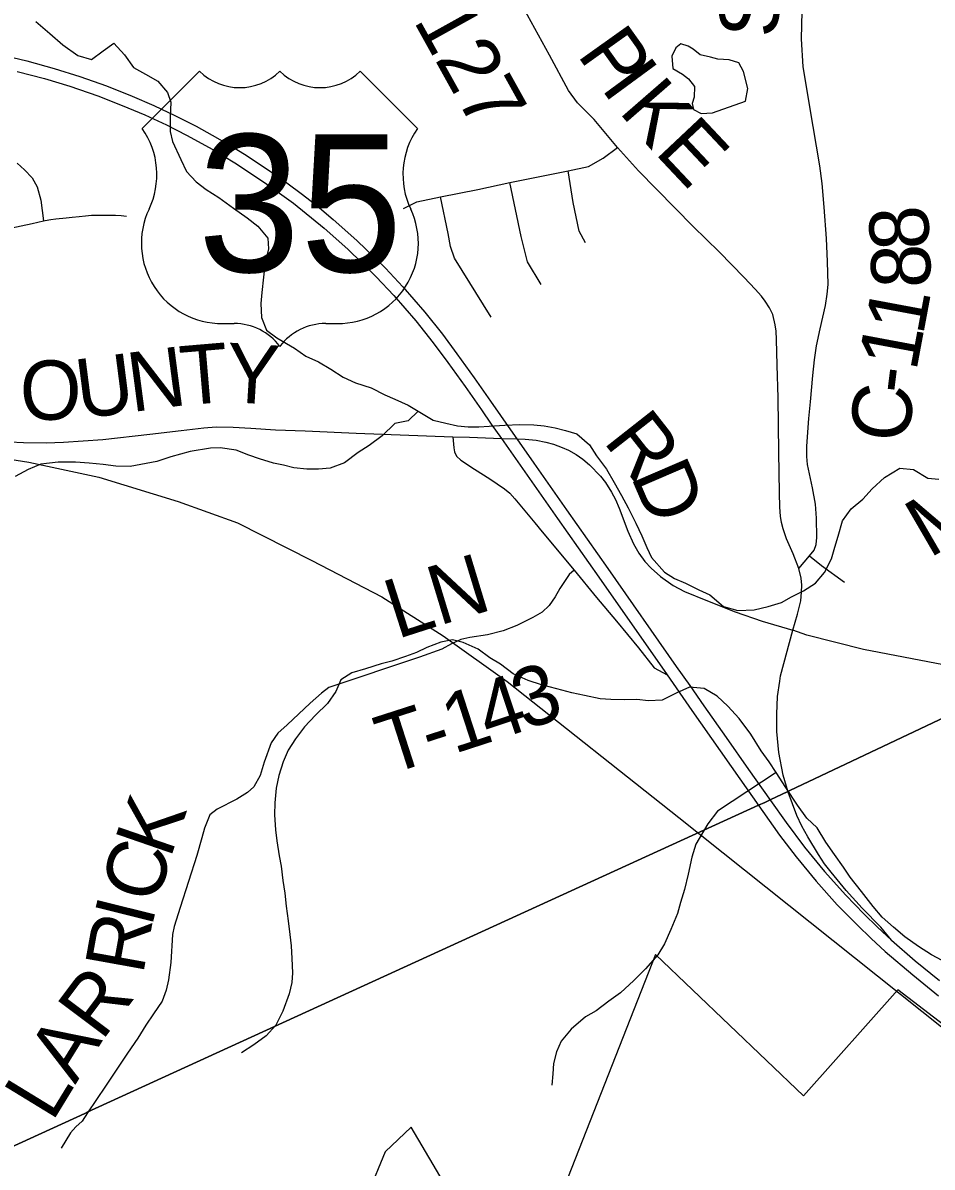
# Model space of a CAD drawing. Extents: x 0 to 34, y 0 to 22.
# Drawn here: x 2.449 to 3.32, y 16.134 to 17.231 of the extents above; entities that cross this region are included whole.
import ezdxf

# ---------------------------------------------------------------- set-up
doc = ezdxf.new("R2010")
doc.units = 0
for name, color, linetype in [('GM_X_Corporation', 7, 'Continuous'), ('GM_X_County_Road', 7, 'Continuous'), ('GM_X_County_Road_Text', 7, 'Continuous'), ('GM_X_Interchange_Ramps', 7, 'Continuous'), ('GM_X_Minor_Lake', 7, 'Continuous'), ('GM_X_Minor_River', 7, 'Continuous'), ('GM_X_Rail_Line', 7, 'Continuous'), ('GM_X_Township_Road', 7, 'Continuous'), ('GM_X_Township_Road_Text', 7, 'Continuous'), ('GM_X_US_Location', 7, 'Continuous'), ('GM_X_US_Route', 7, 'Continuous'), ('GM_X_US_Shield', 7, 'Continuous'), ('SH_Data', 7, 'Continuous')]:
    doc.layers.add(name, color=color, linetype=linetype)

msp = doc.modelspace()

# ---------------------------------------------------------------- linework, layer by layer
at = {"layer": 'GM_X_Corporation'}
for points in [[(2.1, 20.9), (2.1, 15.9991), (2.5081, 16.1858), (2.5106, 16.1869), (3.1538, 16.4811), (3.1598, 16.4838), (3.1648, 16.4862), (3.1819, 16.4943), (3.1836, 16.4951), (3.3801, 16.588), (3.8146, 16.7867), (3.8864, 16.8187), (4.2007, 16.9645), (4.2041, 17.0039), (4.5514, 17.1703), (4.4931, 17.1874), (4.4442, 17.208), (4.4091, 17.232)], [(3.3801, 16.588), (3.1836, 16.4951), (3.1819, 16.4943), (3.1648, 16.4862), (3.1598, 16.4838), (3.1538, 16.4811), (2.5106, 16.1869), (2.5081, 16.1858), (2.1, 15.9991), (2.1, 14.1), (7.2283, 14.1)], [(3.5673, 16.0897), (3.2872, 16.3043), (3.197, 16.2026), (3.0551, 16.3381), (2.9469, 16.0625), (2.8663, 16.0956), (2.8209, 16.1726), (2.7961, 16.1489), (2.7147, 15.9511), (2.6512, 15.9557), (2.5715, 15.9232), (2.6113, 15.828), (2.6287, 15.7341), (2.5959, 15.6539), (2.3763, 15.7531), (2.1188, 15.8705), (2.1, 15.8606), (2.1, 15.2015)]]:
    msp.add_lwpolyline(points, dxfattribs=at)
at = {"layer": 'GM_X_County_Road'}
for points in [[(3.1924, 16.708), (3.2025, 16.7202), (3.207, 16.7256), (3.209, 16.7308), (3.2097, 16.7375), (3.2092, 16.7562), (3.2082, 16.7695), (3.2056, 16.7852), (3.2026, 16.7986), (3.2007, 16.8076), (3.2, 16.8152), (3.2, 16.825), (3.2019, 16.8517), (3.2035, 16.8677), (3.2059, 16.8929), (3.2074, 16.908), (3.2094, 16.9214), (3.2129, 16.9376), (3.2178, 16.96), (3.2196, 16.9707), (3.2204, 16.9799), (3.2197, 17.0022), (3.2188, 17.024), (3.2168, 17.0542), (3.2147, 17.0769), (3.2125, 17.0938), (3.2061, 17.1313), (3.1965, 17.1886), (3.1948, 17.2155), (3.1976, 17.3201)], [(3.1865, 16.6487), (3.191, 16.6643), (3.1943, 16.6769), (3.195, 16.6852), (3.1952, 16.6921), (3.1947, 16.6988), (3.1924, 16.708), (3.1869, 16.7219), (3.1807, 16.7362), (3.1774, 16.7458), (3.1757, 16.7519), (3.1748, 16.7581), (3.1743, 16.7666), (3.1739, 16.7803), (3.1733, 16.8195), (3.1725, 16.8716), (3.1717, 16.9026), (3.1711, 16.9274), (3.1706, 16.9353), (3.1698, 16.9415), (3.1673, 16.9512), (3.1644, 16.9577), (3.1601, 16.964), (3.1566, 16.9688), (3.1504, 16.9757), (3.14, 16.9867), (3.1161, 17.0114), (3.0912, 17.0356), (3.0386, 17.089), (3.0186, 17.1112), (2.9961, 17.1381), (2.9803, 17.154), (2.9717, 17.166), (2.9533, 17.1998), (2.9112, 17.2768)], [(2.4362, 16.8293), (2.4495, 16.8285), (2.4713, 16.8284), (2.4877, 16.8289), (2.5255, 16.8316), (2.5704, 16.8367), (2.6005, 16.8402), (2.6222, 16.8428), (2.634, 16.8437), (2.6505, 16.8433), (2.6674, 16.8423), (2.6909, 16.8409), (2.7192, 16.8397), (2.7683, 16.8377), (2.8609, 16.8342), (2.8769, 16.8337), (2.9074, 16.8326), (2.9221, 16.8321), (2.9302, 16.8318), (2.9407, 16.8308), (2.9498, 16.8291), (2.9573, 16.8272), (2.9657, 16.824), (2.9717, 16.8213), (2.979, 16.8172), (2.9854, 16.8127), (2.9919, 16.8071), (3.0023, 16.7964), (3.007, 16.7903), (3.0128, 16.7812), (3.0168, 16.774), (3.0201, 16.7657), (3.0284, 16.7436), (3.0338, 16.7314), (3.039, 16.7227), (3.0449, 16.7147), (3.0508, 16.7084), (3.0599, 16.7001), (3.072, 16.6916), (3.0827, 16.686), (3.1047, 16.677), (3.1314, 16.6663), (3.1573, 16.6576), (3.1865, 16.6487)], [(3.2025, 16.7202), (3.2141, 16.7109), (3.236, 16.6948)], [(3.3378, 16.6142), (3.3161, 16.6186), (3.2542, 16.6304), (3.1999, 16.6441), (3.1865, 16.6487)]]:
    msp.add_lwpolyline(points, dxfattribs=at)
at = {"layer": 'GM_X_Interchange_Ramps'}
for points in [[(2.9772, 16.7064), (2.9986, 16.6802), (3.0175, 16.6576), (3.0386, 16.6318), (3.0539, 16.6129), (3.0662, 16.6059)], [(3.1741, 16.5999), (3.1749, 16.6051), (3.1865, 16.6487)], [(3.2811, 16.3517), (3.2709, 16.3642), (3.2532, 16.3824), (3.2377, 16.3995), (3.2233, 16.4169), (3.2171, 16.425), (3.2111, 16.434), (3.2009, 16.4507), (3.1953, 16.461), (3.1906, 16.4713), (3.1821, 16.4937), (3.1775, 16.5099), (3.1733, 16.5316), (3.1714, 16.5518), (3.1712, 16.5682), (3.172, 16.5854), (3.1741, 16.5999)]]:
    msp.add_lwpolyline(points, dxfattribs=at)
at = {"layer": 'GM_X_Minor_Lake'}
for points in [[(3.1413, 17.1556), (3.1434, 17.1677), (3.1394, 17.1841), (3.1349, 17.1924), (3.1255, 17.1952), (3.1149, 17.196), (3.1077, 17.198), (3.0979, 17.2), (3.0911, 17.2054), (3.0862, 17.2085), (3.0794, 17.2108), (3.0745, 17.2067), (3.0706, 17.1987), (3.0716, 17.187), (3.081, 17.1816), (3.0866, 17.177), (3.0923, 17.1697), (3.0921, 17.1594), (3.0902, 17.1534), (3.0916, 17.1477), (3.0988, 17.1438), (3.1098, 17.1445)], [(3.1098, 17.1445), (3.1413, 17.1556)]]:
    msp.add_lwpolyline(points, dxfattribs=at)
at = {"layer": 'GM_X_Minor_River'}
for points in [[(2.4612, 17.232), (2.4747, 17.2205), (2.4871, 17.2098), (2.5014, 17.1994), (2.5146, 17.1955), (2.5257, 17.2041), (2.536, 17.2112), (2.5461, 17.2001), (2.5547, 17.1879), (2.5663, 17.1817), (2.578, 17.1748), (2.5874, 17.1641), (2.5907, 17.1546), (2.5901, 17.1405), (2.59, 17.1265), (2.5922, 17.117), (2.6003, 17.0998), (2.6055, 17.0884), (2.6149, 17.0785), (2.6246, 17.0712), (2.6367, 17.0635), (2.6506, 17.0531), (2.6637, 17.0439), (2.6739, 17.0358), (2.6836, 17.0243), (2.6843, 17.0141), (2.6811, 17.0012), (2.6794, 16.9872), (2.6778, 16.9724), (2.6769, 16.9618), (2.6775, 16.9485), (2.6823, 16.9363), (2.6921, 16.929), (2.709, 16.919), (2.7199, 16.9113), (2.732, 16.9059), (2.744, 16.8989), (2.7557, 16.8912), (2.7677, 16.8858), (2.7825, 16.8811), (2.7956, 16.8742), (2.8054, 16.8703), (2.8179, 16.8645), (2.8277, 16.8587), (2.842, 16.8502), (2.8541, 16.8471), (2.8654, 16.8447), (2.8756, 16.8438), (2.8858, 16.8437), (2.8957, 16.8444), (2.9108, 16.8454), (2.9249, 16.846), (2.9385, 16.8455), (2.9483, 16.8447), (2.9589, 16.8427), (2.9687, 16.8403), (2.9797, 16.8368), (2.9917, 16.8265), (2.9984, 16.8158), (3.0081, 16.8032), (3.0155, 16.7902), (3.0226, 16.778), (3.0289, 16.7662), (3.0363, 16.7513), (3.0419, 16.7391), (3.0467, 16.7281), (3.0512, 16.7185), (3.0635, 16.7044), (3.0733, 16.6982), (3.0838, 16.6939), (3.0967, 16.6874), (3.1072, 16.6827), (3.1203, 16.6716), (3.1339, 16.6677), (3.1495, 16.6683), (3.1631, 16.6716), (3.1757, 16.6753), (3.1852, 16.6809), (3.197, 16.6864), (3.2084, 16.6939), (3.2169, 16.7041), (3.2238, 16.7173), (3.227, 16.7283), (3.2301, 16.7389), (3.2341, 16.7536), (3.2425, 16.765), (3.2536, 16.7743), (3.2628, 16.7841), (3.2743, 16.795), (3.2891, 16.804), (3.3024, 16.8027), (3.3159, 16.7946), (3.3265, 16.7934)], [(2.8277, 16.8587), (2.8181, 16.8493), (2.8052, 16.8468), (2.793, 16.8351), (2.7807, 16.8257), (2.7701, 16.819), (2.7571, 16.8093), (2.7434, 16.8041), (2.732, 16.803), (2.721, 16.8031), (2.7086, 16.8044), (2.6987, 16.8068), (2.6889, 16.8088), (2.6757, 16.813), (2.6655, 16.8166), (2.6531, 16.8212), (2.6379, 16.8236), (2.6285, 16.8233), (2.6091, 16.8201), (2.5905, 16.815), (2.5772, 16.8105), (2.567, 16.8084), (2.5518, 16.8055), (2.5378, 16.806), (2.5257, 16.8076), (2.5124, 16.8089), (2.4992, 16.8097), (2.4825, 16.8099), (2.4662, 16.8078), (2.454, 16.8029), (2.4415, 16.7962)], [(3.3296, 16.3323), (3.3195, 16.3377), (3.307, 16.3458), (3.2939, 16.3551), (3.283, 16.3643), (3.2721, 16.3738), (3.2635, 16.3842), (3.2523, 16.3983), (3.2415, 16.4121), (3.2351, 16.4216), (3.2265, 16.4338), (3.2183, 16.4457), (3.2098, 16.4594), (3.2, 16.4686), (3.1911, 16.4812), (3.1799, 16.498), (3.1706, 16.5125), (3.1638, 16.5228), (3.1564, 16.5331), (3.1463, 16.5492), (3.1351, 16.5641), (3.1243, 16.5759), (3.1141, 16.5855), (3.1017, 16.5928), (3.0877, 16.5941), (3.0748, 16.5885), (3.0615, 16.5818), (3.0482, 16.5812), (3.0372, 16.5824), (3.0251, 16.5822), (3.0122, 16.5823), (3.002, 16.5831), (2.9869, 16.5863), (2.9748, 16.5887), (2.9605, 16.5926), (2.9457, 16.5966), (2.9329, 16.6005), (2.9186, 16.607), (2.9065, 16.6163), (2.8964, 16.6224), (2.8851, 16.6305), (2.8708, 16.6371), (2.8606, 16.6395), (2.8492, 16.6373), (2.8359, 16.6321), (2.826, 16.6273), (2.8154, 16.6236), (2.8024, 16.6191), (2.7922, 16.6166), (2.777, 16.6118), (2.7641, 16.6081), (2.7534, 16.6014), (2.7487, 16.59), (2.7407, 16.5787), (2.7292, 16.5674), (2.7188, 16.5561), (2.71, 16.5448), (2.7031, 16.5339), (2.6984, 16.5226), (2.6941, 16.5097), (2.6917, 16.4976), (2.6904, 16.4835), (2.6899, 16.4718), (2.6909, 16.4574), (2.6923, 16.4471), (2.6944, 16.4327), (2.6962, 16.4228), (2.698, 16.4091)], [(3.1706, 16.5125), (3.1145, 16.4755), (3.1053, 16.4634), (3.0937, 16.4438), (3.0898, 16.4313), (3.0862, 16.415), (3.0827, 16.4003), (3.0791, 16.3878), (3.076, 16.3775), (3.0698, 16.362), (3.0635, 16.3484), (3.0574, 16.3379), (3.0455, 16.3243), (3.0344, 16.313), (3.0214, 16.3014), (3.0103, 16.2935), (2.9981, 16.2842), (2.9878, 16.2782), (2.9741, 16.2665), (2.9645, 16.2549), (2.9602, 16.2447), (2.9574, 16.2337), (2.9566, 16.2238), (2.9557, 16.2128)], [(2.698, 16.4091), (2.6997, 16.3969), (2.7011, 16.3844), (2.7029, 16.3704), (2.7046, 16.3571), (2.706, 16.3464), (2.7066, 16.3343), (2.7073, 16.3206), (2.7064, 16.3111), (2.704, 16.3005), (2.6978, 16.2839), (2.6912, 16.2703), (2.682, 16.2601), (2.6702, 16.2515), (2.6584, 16.244)]]:
    msp.add_lwpolyline(points, dxfattribs=at)
at = {"layer": 'GM_X_Rail_Line'}
msp.add_lwpolyline([(2.1, 16.8228), (2.1358, 16.8282), (2.1875, 16.8321), (2.2635, 16.8323), (2.3249, 16.8251), (2.3996, 16.8184), (2.4546, 16.8097), (2.5216, 16.7954), (2.5976, 16.772), (2.6544, 16.7517), (2.7256, 16.7157), (2.7928, 16.6809), (2.8517, 16.6435), (2.9129, 16.5996), (3.0775, 16.4694), (3.2031, 16.3691), (3.3322, 16.2662), (3.4651, 16.1627), (3.5695, 16.0783), (3.7315, 15.9489), (3.9997, 15.7391), (4.1856, 15.5884)], dxfattribs=at)
at = {"layer": 'GM_X_Township_Road'}
for points in [[(2.8136, 17.053), (2.8263, 17.0594), (2.8489, 17.0639), (2.8849, 17.071), (2.9154, 17.0778), (2.9713, 17.089), (2.9909, 17.0932), (3.0048, 17.101), (3.0186, 17.1112)], [(2.4433, 17.0963), (2.4505, 17.0899), (2.4579, 17.0821), (2.4624, 17.0736), (2.466, 17.0607), (2.4687, 17.041)], [(2.9878, 17.0199), (2.9818, 17.0312), (2.9762, 17.0586), (2.9713, 17.089)], [(2.9454, 16.9801), (2.9323, 17.0019), (2.9262, 17.0259), (2.9154, 17.0778)], [(2.8977, 16.9489), (2.8624, 17.0053), (2.8586, 17.0165), (2.8564, 17.0289), (2.8489, 17.0639)], [(2.1654, 17.0008), (2.2496, 16.9966), (2.276, 16.9998), (2.2982, 17.0045), (2.3732, 17.0205), (2.3897, 17.024), (2.4577, 17.0384), (2.4687, 17.041)], [(2.4687, 17.041), (2.4738, 17.0421), (2.4755, 17.0424), (2.4803, 17.043), (2.4902, 17.044), (2.496, 17.0447), (2.5029, 17.0453), (2.5088, 17.0459), (2.5146, 17.0464), (2.5227, 17.0466), (2.5375, 17.0465), (2.5431, 17.0461), (2.5482, 17.0454)], [(2.8609, 16.8342), (2.8617, 16.8237), (2.8623, 16.8198), (2.8643, 16.8155), (2.8686, 16.8117), (2.8816, 16.803), (2.8964, 16.7938), (2.9102, 16.7844), (2.9153, 16.78), (2.9202, 16.7746), (2.9393, 16.7516)], [(2.9393, 16.7516), (2.9463, 16.7432), (2.9772, 16.7064), (2.9722, 16.7023), (2.9632, 16.6889), (2.9588, 16.6809), (2.9532, 16.6725), (2.9463, 16.6661), (2.9375, 16.661), (2.9222, 16.6533), (2.9092, 16.6482), (2.894, 16.6444), (2.8771, 16.6418), (2.8686, 16.6398), (2.8596, 16.6358), (2.8503, 16.6307), (2.829, 16.6231), (2.742, 16.594), (2.7349, 16.5885), (2.7242, 16.5788), (2.7021, 16.5581), (2.6931, 16.55), (2.6866, 16.5409), (2.6802, 16.5224), (2.6763, 16.5096), (2.6702, 16.4986), (2.6641, 16.4934), (2.6539, 16.487), (2.6351, 16.4773), (2.628, 16.4718), (2.6228, 16.4592), (2.6204, 16.4498), (2.6156, 16.4328), (2.5995, 16.383)], [(2.5995, 16.383), (2.5937, 16.365), (2.5921, 16.3573), (2.5906, 16.3305), (2.5885, 16.3139), (2.5862, 16.3038), (2.5822, 16.2934), (2.5741, 16.2812), (2.5668, 16.2705), (2.5589, 16.2579), (2.5491, 16.2436), (2.5279, 16.212), (2.5108, 16.1864), (2.5055, 16.1784), (2.4996, 16.1728), (2.4946, 16.1672), (2.4856, 16.1526)]]:
    msp.add_lwpolyline(points, dxfattribs=at)
at = {"layer": 'GM_X_US_Route'}
for points in [[(2.4268, 17.2005), (2.4526, 17.1943), (2.4789, 17.1871), (2.5034, 17.1794), (2.5289, 17.1703), (2.5535, 17.1605), (2.5742, 17.1516), (2.595, 17.1417), (2.6149, 17.1317), (2.6352, 17.1204), (2.6482, 17.1129), (2.6611, 17.1049), (2.6868, 17.088), (2.7019, 17.0776), (2.7167, 17.0662), (2.7308, 17.0553), (2.7462, 17.0424), (2.7688, 17.0223), (2.7962, 16.9957), (2.8129, 16.9779), (2.8341, 16.9536), (2.8508, 16.9324), (2.8648, 16.9136), (2.8812, 16.8906), (2.8969, 16.8681), (2.9065, 16.8546), (2.9161, 16.8409), (2.9221, 16.8321), (2.9384, 16.809), (2.9698, 16.7641), (3.0093, 16.7078), (3.0749, 16.6141), (3.0878, 16.5959), (3.1015, 16.5764), (3.1227, 16.546), (3.1443, 16.5154), (3.1651, 16.4857), (3.1803, 16.4644), (3.1979, 16.4409), (3.2171, 16.4175), (3.2373, 16.3948), (3.2545, 16.377), (3.2678, 16.3641), (3.2811, 16.3517)], [(2.4435, 17.1842), (2.4697, 17.1774), (2.4939, 17.17), (2.5206, 17.1609), (2.5441, 17.1516), (2.5656, 17.1425), (2.5864, 17.1329), (2.6055, 17.1231), (2.6308, 17.1093), (2.652, 17.0967), (2.6803, 17.0779), (2.708, 17.0579), (2.7375, 17.0341), (2.7601, 17.014), (2.7875, 16.9874), (2.8042, 16.9696), (2.8254, 16.9453), (2.8421, 16.9242), (2.8561, 16.9053), (2.8725, 16.8823), (2.8882, 16.8598), (2.8977, 16.8463), (2.9074, 16.8326), (2.9297, 16.8007), (2.9611, 16.7558), (3.0006, 16.6995), (3.0662, 16.6059)], [(3.0662, 16.6059), (3.0899, 16.5718), (3.1359, 16.5063), (3.154, 16.4805), (3.1578, 16.4751), (3.1739, 16.4524), (3.1898, 16.4317), (3.209, 16.4084), (3.2292, 16.3857), (3.2485, 16.3662), (3.2617, 16.3533), (3.2751, 16.3409), (3.3015, 16.3185), (3.3261, 16.2986)], [(3.2811, 16.3517), (3.3038, 16.332), (3.3273, 16.313)]]:
    msp.add_lwpolyline(points, dxfattribs=at)
at = {"layer": 'GM_X_US_Shield'}
for p, q in [((2.6182, 17.1844), (2.5633, 17.1295)), ((2.8269, 17.1295), (2.772, 17.1844)), ((2.6402, 16.9427), (2.6512, 16.9427)), ((2.739, 16.9427), (2.75, 16.9427))]:
    msp.add_line(p, q, dxfattribs=at)
for centre, radius, start, end in [((2.6566, 17.2236), 0.0549, 225.573, 314.427), ((2.7336, 17.2236), 0.0549, 225.573, 314.427), ((2.5003, 17.0853), 0.0769, 334.5471, 35.0009), ((2.8899, 17.0853), 0.0769, 144.9991, 205.4529), ((2.6393, 17.0196), 0.0769, 154.8319, 270.6383), ((2.7509, 17.0196), 0.0769, 269.3617, 25.1681), ((2.6512, 16.8878), 0.0549, 36.8699, 90), ((2.739, 16.8878), 0.0549, 90, 143.1301)]:
    msp.add_arc(centre, radius, start, end, dxfattribs=at)
at = {"layer": 'SH_Data'}
for p, q in [((2.6182, 17.1844), (2.5633, 17.1295)), ((2.8269, 17.1295), (2.772, 17.1844)), ((2.6402, 16.9427), (2.6512, 16.9427)), ((2.739, 16.9427), (2.75, 16.9427))]:
    msp.add_line(p, q, dxfattribs=at)
for centre, radius, start, end in [((2.6566, 17.2236), 0.0549, 225.573, 314.427), ((2.7336, 17.2236), 0.0549, 225.573, 314.427), ((2.5003, 17.0853), 0.0769, 334.5471, 35.0009), ((2.8899, 17.0853), 0.0769, 144.9991, 205.4529), ((2.6393, 17.0196), 0.0769, 154.8319, 270.6383), ((2.7509, 17.0196), 0.0769, 269.3617, 25.1681), ((2.6512, 16.8878), 0.0549, 36.8699, 90), ((2.739, 16.8878), 0.0549, 90, 143.1301)]:
    msp.add_arc(centre, radius, start, end, dxfattribs=at)

# ---------------------------------------------------------------- texts
at = {"layer": 'GM_X_County_Road_Text'}
for s, height, rotation, p in [('C-127', 0.05682, 299.03, (2.7836, 17.3032)), ('S', 0.0568, 88.6267, (3.1727, 17.2164)), ('P', 0.0568, 305.5128, (2.9791, 17.2005)), ('I', 0.0568, 306.2978, (3.0019, 17.1686)), ('K', 0.0568, 311.0219, (3.0189, 17.1458)), ('E', 0.0568, 313.2608, (3.0533, 17.1064)), ('8', 0.0568, 93.5024, (3.3181, 17.0149)), ('8', 0.0568, 90.935, (3.3188, 16.9771)), ('1', 0.0568, 79.4154, (3.3113, 16.9303)), ('1', 0.0568, 79.3912, (3.3048, 16.8959)), ('N', 0.0568, 7.4844, (2.553, 16.8577)), ('T', 0.0568, 4.8658, (2.6019, 16.8641)), ('Y', 0.0568, 356.5336, (2.6421, 16.8677)), ('O', 0.0568, 0.935, (2.4464, 16.85)), ('U', 0.0568, 7.3098, (2.5033, 16.8513)), ('-', 0.0568, 82.996, (3.3021, 16.8737)), ('C', 0.0568, 84.4844, (3.2977, 16.8276)), ('R', 0.0568, 308.1783, (3.0041, 16.8298)), ('D', 0.0568, 293.3182, (3.0309, 16.7965)), ('M', 0.0568, 30.1259, (3.3173, 16.7173))]:
    msp.add_text(s, height=height, rotation=rotation, dxfattribs=at).set_placement(p)
at = {"layer": 'GM_X_Township_Road_Text'}
for s, rotation, p in [('N', 16.9061, (2.8475, 16.653)), ('L', 17.8007, (2.8073, 16.6401)), ('3', 19.4983, (2.9298, 16.5525)), ('4', 18.3834, (2.8955, 16.541)), ('1', 17.9993, (2.8618, 16.5301)), ('T', 17.8549, (2.799, 16.5099)), ('-', 17.8702, (2.8394, 16.5229)), ('K', 70.9487, (2.59, 16.429)), ('C', 74.1441, (2.5775, 16.385)), ('I', 76.0452, (2.572, 16.3628)), ('R', 79.7667, (2.5639, 16.3178)), ('R', 53.1465, (2.5245, 16.2543)), ('A', 58.2441, (2.499, 16.2129)), ('L', 58.5688, (2.4769, 16.1767))]:
    msp.add_text(s, height=0.0568, rotation=rotation, dxfattribs=at).set_placement(p)
at = {"layer": 'GM_X_US_Location'}
for s in ['0', '/']:
    msp.add_text(s, height=0.000189, dxfattribs=at).set_placement((2.695, 17.057))
msp.add_text('35', height=0.000189, rotation=0, dxfattribs=at).set_placement((2.6559, 17.0178))
at = {"layer": 'GM_X_US_Shield'}
msp.add_text('35', height=0.13184, dxfattribs=at).set_placement((2.6165, 16.9921))
at = {"layer": 'SH_Data'}
msp.add_text('35', height=0.13184, dxfattribs=at).set_placement((2.6165, 16.9921))

doc.saveas('drawing.dxf')
